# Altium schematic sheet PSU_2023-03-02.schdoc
size 188 x 247 mm
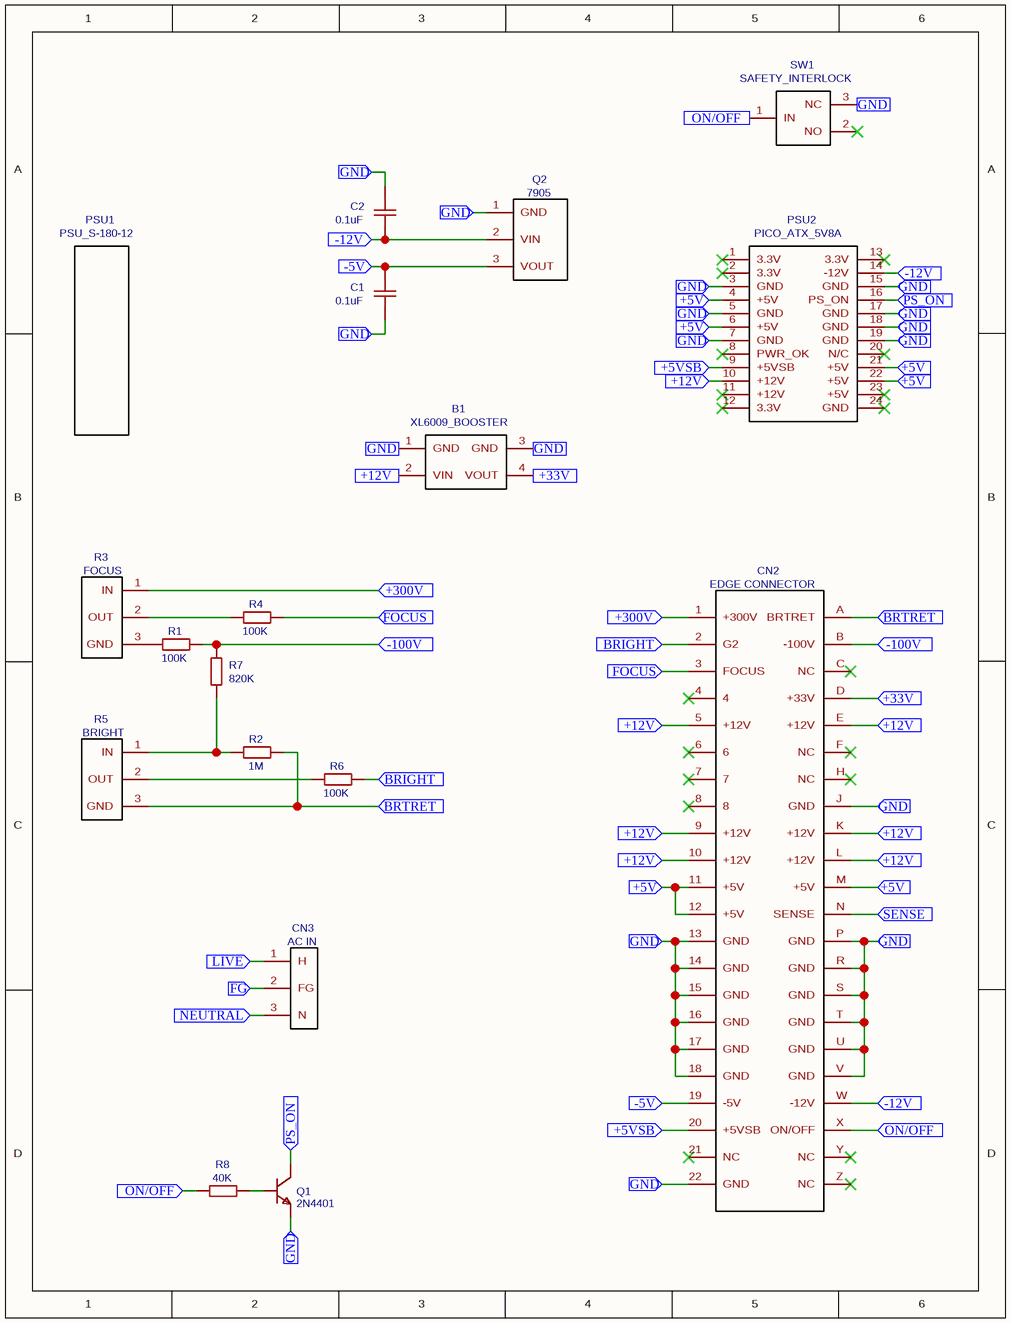
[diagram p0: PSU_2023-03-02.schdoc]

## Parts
B1  XL6009_BOOSTER  [XL6009_BOOSTER]
C1  0.1uF  [LISA_DISC_CERAMIC_CAPACITOR]
C2  0.1uF  [LISA_DISC_CERAMIC_CAPACITOR]
CN2  EDGE CONNECTOR  [LISA_PSU_EDGE_CONNECTOR]
CN3  AC IN  [LISA_PSU_AC_IN]
PSU1  PSU_S-180-12  [PSU_S-180-12]
PSU2  PICO_ATX_5V8A  [PICO_ATX_5V8A]
Q1  2N4401  [TO-92-3_L4.9-W3.7-P1.27-L]
Q2  7905  [TO-220]
R1  100K  [LISA_RESISTOR]
R2  1M  [LISA_RESISTOR]
R3  FOCUS  [LISA_CRT_POT]
R4  100K  [LISA_RESISTOR]
R5  BRIGHT  [LISA_CRT_POT]
R6  100K  [LISA_RESISTOR]
R7  820K  [LISA_RESISTOR]
R8  40K  [LISA_RESISTOR]
SW1  SAFETY_INTERLOCK  [111SM1_LEAF_SWITCH]

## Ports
+5V (in), +5VSB (in), +12V (in), +33V (in), +300V (in), -5V (in), -12V (in), -100V (in), BRIGHT (in), BRTRET (in), FG (in), FOCUS (in), GND (in), LIVE (in), NEUTRAL (in), ON/OFF (in), PS_ON (in), SENSE (in)

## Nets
+5V: CN2.11(+5V) CN2.12(+5V) CN2.M(+5V) PSU2.4(+5V) PSU2.6(+5V) PSU2.21(+5V) PSU2.22(+5V) ; port +5V
+5VSB: CN2.20(+5VSB) PSU2.9(+5VSB) ; port +5VSB
+12V: B1.2(VIN) CN2.5(+12V) CN2.9(+12V) CN2.10(+12V) CN2.E(+12V) CN2.K(+12V) CN2.L(+12V) PSU2.10(+12V) ; port +12V
+33V: B1.4(VOUT) CN2.D(+33V) ; port +33V
+300V: CN2.1(+300V) R3.1(IN) ; port +300V
-5V: C1.1 CN2.19(-5V) Q2.3(VOUT) ; port -5V
-12V: C2.2 CN2.W(-12V) PSU2.14(-12V) Q2.2(VIN) ; port -12V
-100V: CN2.B(-100V) R1.2 R7.1 ; port -100V
BRIGHT: CN2.2(G2) R6.1 ; port BRIGHT
BRTRET: CN2.A(BRTRET) R2.1 R5.3(GND) ; port BRTRET
FG: CN3.2(FG) ; port FG
FOCUS: CN2.3(FOCUS) R4.1 ; port FOCUS
GND: B1.1(GND) B1.3(GND) C1.2 C2.1 CN2.13(GND) CN2.14(GND) CN2.15(GND) CN2.16(GND) CN2.17(GND) CN2.18(GND) CN2.22(GND) CN2.J(GND) CN2.P(GND) CN2.R(GND) CN2.S(GND) CN2.T(GND) CN2.U(GND) CN2.V(GND) PSU2.3(GND) PSU2.5(GND) PSU2.7(GND) PSU2.15(GND) PSU2.17(GND) PSU2.18(GND) PSU2.19(GND) Q1.1(E) Q2.1(GND) SW1.3(NC) ; port GND
LIVE: CN3.1(H) ; port LIVE
NEUTRAL: CN3.3(N) ; port NEUTRAL
ON/OFF: CN2.X(ON/OFF) R8.1 SW1.1(IN) ; port ON/OFF
PS_ON: PSU2.16(PS_ON) Q1.3(C) ; port PS_ON
SENSE: CN2.N(SENSE) ; port SENSE
NetQ1_2: Q1.2(B) R8.2
NetR1_1: R1.1 R3.3(GND)
NetR2_2: R2.2 R5.1(IN) R7.2
NetR3_2: R3.2(OUT) R4.2
NetR5_2: R5.2(OUT) R6.2

Not connected (* = marked no-connect by the designer): CN2 4* 6* 7* 8* 21(NC)* C(NC)* F(NC)* H(NC)* Y(NC)* Z(NC)*; PSU2 1(3.3V)* 2(3.3V)* 8(PWR_OK)* 11(+12V)* 12(3.3V)* 13(3.3V)* 20(N/C)* 23(+5V)* 24(GND)*; SW1 2(NO)*

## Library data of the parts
B1 = XL6009_BOOSTER: Contributor: William Tooker
C1 C2 = 0.1uF: Contributor: William Tooker
CN2 = EDGE CONNECTOR: Contributor: will_tooker
CN3 = AC IN: Contributor: William Tooker
PSU1 = PSU_S-180-12: Contributor: William Tooker
PSU2 = PICO_ATX_5V8A: Contributor: William Tooker
Q1 = 2N4401: BOM_Manufacturer: ST(先科); Contributor: 立创EDA官方封装库
Q2 = 7905: Contributor: will_tooker
R1 R4 R6 = 100K: Contributor: William Tooker
R2 = 1M: Contributor: William Tooker
R3 = FOCUS: Contributor: William Tooker
R5 = BRIGHT: Contributor: William Tooker
R7 = 820K: Contributor: William Tooker
R8 = 40K: Contributor: William Tooker
SW1 = SAFETY_INTERLOCK: Contributor: William Tooker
